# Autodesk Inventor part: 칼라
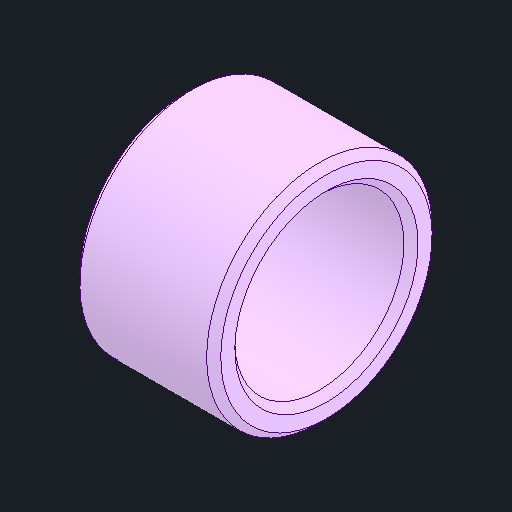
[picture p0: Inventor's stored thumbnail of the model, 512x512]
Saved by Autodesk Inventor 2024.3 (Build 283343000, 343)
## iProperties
Created: 2024-05
Part Number: 칼라
Material: 강철, 합금
Document SubType Name: Modeling
Designer: MyPc
Density: 7.73 g/cm^3
Appearance: 기본값
Author: jhkim
Sending System: Autodesk Inventor 2025
Preprocessor: ST-DEVELOPER v20
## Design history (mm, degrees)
node "칼라1"
node "솔리드2"
node "솔리드1"
